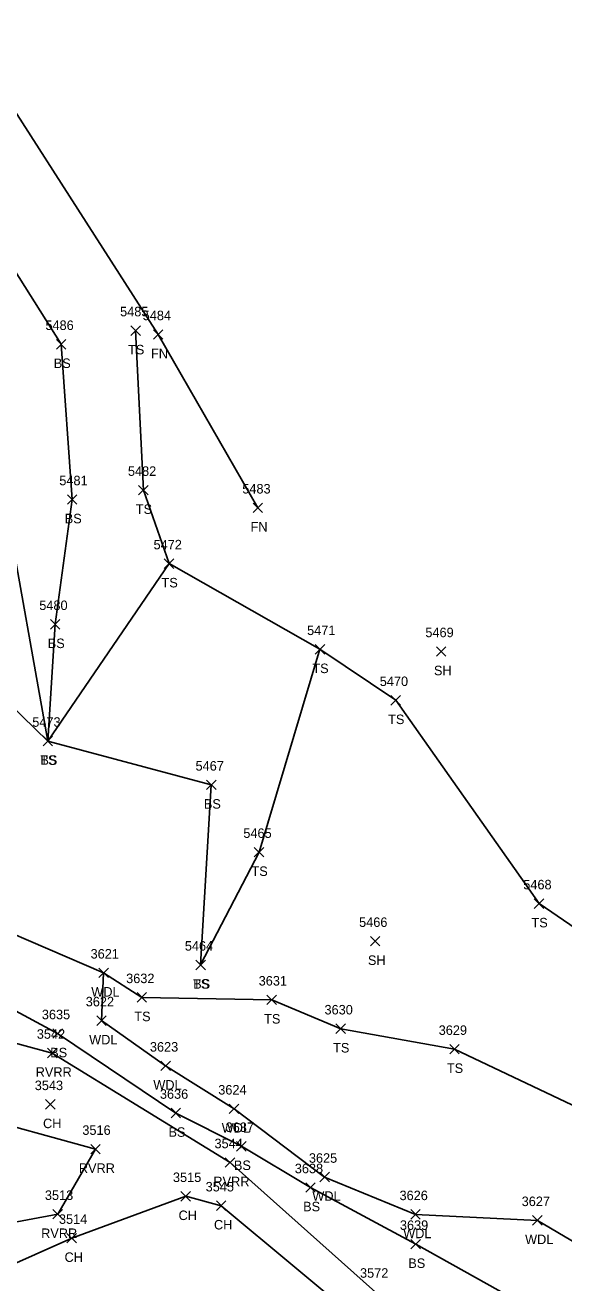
# Model space of a CAD drawing. Extents: x 1601151 to 1602912, y 499508 to 501770.
# Drawn here: x 1601662.3 to 1601775.4, y 500689.8 to 500954.3 of the extents above; entities that cross this region are included whole.
import ezdxf

# ---------------------------------------------------------------- set-up
doc = ezdxf.new("R2010")
doc.units = 0
for name, color, linetype in [('L_A', 7, 'Continuous'), ('L_I', 7, 'Continuous'), ('L_TIC', 7, 'Continuous'), ('LAWA', 7, 'Continuous'), ('LAWE', 7, 'Continuous'), ('LDEFAULT', 7, 'Continuous'), ('LELB', 7, 'Continuous'), ('LFNC', 7, 'Continuous')]:
    doc.layers.add(name, color=color, linetype=linetype)

msp = doc.modelspace()

# ---------------------------------------------------------------- linework, layer by layer
at = {"layer": 'L_TIC'}
for points in [[(1601684.45, 500889.07), (1601686.45, 500891.07)], [(1601686.45, 500889.07), (1601684.45, 500891.07)], [(1601689.2, 500888.26), (1601691.2, 500890.26)], [(1601691.2, 500888.26), (1601689.2, 500890.26)], [(1601668.81, 500886.2), (1601670.81, 500888.2)], [(1601670.81, 500886.2), (1601668.81, 500888.2)], [(1601686.09, 500855.52), (1601688.09, 500857.52)], [(1601688.09, 500855.52), (1601686.09, 500857.52)], [(1601671.12, 500853.54), (1601673.12, 500855.54)], [(1601673.12, 500853.54), (1601671.12, 500855.54)], [(1601710.12, 500851.81), (1601712.12, 500853.81)], [(1601712.12, 500851.81), (1601710.12, 500853.81)], [(1601691.48, 500840.06), (1601693.48, 500842.06)], [(1601693.48, 500840.06), (1601691.48, 500842.06)], [(1601691.48, 500840.06), (1601693.48, 500842.06)], [(1601693.48, 500840.06), (1601691.48, 500842.06)], [(1601667.55, 500827.3), (1601669.55, 500829.3)], [(1601669.55, 500827.3), (1601667.55, 500829.3)], [(1601723.17, 500822.04), (1601725.17, 500824.04)], [(1601725.17, 500822.04), (1601723.17, 500824.04)], [(1601723.17, 500822.04), (1601725.17, 500824.04)], [(1601725.17, 500822.04), (1601723.17, 500824.04)], [(1601748.64, 500821.59), (1601750.64, 500823.59)], [(1601750.64, 500821.59), (1601748.64, 500823.59)], [(1601739.09, 500811.32), (1601741.09, 500813.32)], [(1601741.09, 500811.32), (1601739.09, 500813.32)], [(1601666, 500802.75), (1601668, 500804.75)], [(1601668, 500802.75), (1601666, 500804.75)], [(1601666, 500802.75), (1601668, 500804.75)], [(1601668, 500802.75), (1601666, 500804.75)], [(1601700.34, 500793.53), (1601702.34, 500795.53)], [(1601702.34, 500793.53), (1601700.34, 500795.53)], [(1601710.38, 500779.38), (1601712.38, 500781.38)], [(1601712.38, 500779.38), (1601710.38, 500781.38)], [(1601769.2, 500768.56), (1601771.2, 500770.56)], [(1601771.2, 500768.56), (1601769.2, 500770.56)], [(1601734.77, 500760.66), (1601736.77, 500762.66)], [(1601736.77, 500760.66), (1601734.77, 500762.66)], [(1601698.1, 500755.67), (1601700.1, 500757.67)], [(1601700.1, 500755.67), (1601698.1, 500757.67)], [(1601698.1, 500755.67), (1601700.1, 500757.67)], [(1601700.1, 500755.67), (1601698.1, 500757.67)], [(1601677.73, 500754.01), (1601679.73, 500756.01)], [(1601679.73, 500754.01), (1601677.73, 500756.01)], [(1601685.77, 500748.84), (1601687.77, 500750.84)], [(1601687.77, 500748.84), (1601685.77, 500750.84)], [(1601713.04, 500748.33), (1601715.04, 500750.33)], [(1601715.04, 500748.33), (1601713.04, 500750.33)], [(1601677.28, 500743.95), (1601679.28, 500745.95)], [(1601679.28, 500743.95), (1601677.28, 500745.95)], [(1601727.53, 500742.25), (1601729.53, 500744.25)], [(1601729.53, 500742.25), (1601727.53, 500744.25)], [(1601668.06, 500741.24), (1601670.06, 500743.24)], [(1601670.06, 500741.24), (1601668.06, 500743.24)], [(1601666.95, 500737.14), (1601668.95, 500739.14)], [(1601668.95, 500737.14), (1601666.95, 500739.14)], [(1601751.43, 500737.95), (1601753.43, 500739.95)], [(1601753.43, 500737.95), (1601751.43, 500739.95)], [(1601690.76, 500734.44), (1601692.76, 500736.44)], [(1601692.76, 500734.44), (1601690.76, 500736.44)], [(1601666.52, 500726.34), (1601668.52, 500728.34)], [(1601668.52, 500726.34), (1601666.52, 500728.34)], [(1601692.91, 500724.52), (1601694.91, 500726.52)], [(1601694.91, 500724.52), (1601692.91, 500726.52)], [(1601705.12, 500725.41), (1601707.12, 500727.41)], [(1601707.12, 500725.41), (1601705.12, 500727.41)], [(1601676.01, 500716.93), (1601678.01, 500718.93)], [(1601678.01, 500716.93), (1601676.01, 500718.93)], [(1601706.66, 500717.53), (1601708.66, 500719.53)], [(1601708.66, 500717.53), (1601706.66, 500719.53)], [(1601704.28, 500714.12), (1601706.28, 500716.12)], [(1601706.28, 500714.12), (1601704.28, 500716.12)], [(1601724.16, 500711.06), (1601726.16, 500713.06)], [(1601726.16, 500711.06), (1601724.16, 500713.06)], [(1601721.2, 500708.86), (1601723.2, 500710.86)], [(1601723.2, 500708.86), (1601721.2, 500710.86)], [(1601694.98, 500707.01), (1601696.98, 500709.01)], [(1601696.98, 500707.01), (1601694.98, 500709.01)], [(1601702.42, 500705.03), (1601704.42, 500707.03)], [(1601704.42, 500705.03), (1601702.42, 500707.03)], [(1601668.09, 500703.24), (1601670.09, 500705.24)], [(1601670.09, 500703.24), (1601668.09, 500705.24)], [(1601743.25, 500703.2), (1601745.25, 500705.2)], [(1601745.25, 500703.2), (1601743.25, 500705.2)], [(1601768.86, 500701.95), (1601770.86, 500703.95)], [(1601770.86, 500701.95), (1601768.86, 500703.95)], [(1601671.03, 500698.21), (1601673.03, 500700.21)], [(1601673.03, 500698.21), (1601671.03, 500700.21)], [(1601743.29, 500696.94), (1601745.29, 500698.94)], [(1601745.29, 500696.94), (1601743.29, 500698.94)]]:
    msp.add_lwpolyline(points, dxfattribs=at)
at = {"layer": 'LAWA'}
msp.add_lwpolyline([(1601593.12, 500801.88), (1601615.83, 500798.98), (1601635.32, 500780.93), (1601655.21, 500765.08), (1601678.73, 500755.01), (1601678.28, 500744.95), (1601691.76, 500735.44), (1601706.12, 500726.41), (1601725.16, 500712.06), (1601744.25, 500704.2), (1601769.86, 500702.95), (1601803.71, 500682.95)], dxfattribs=at)
at = {"layer": 'LAWE'}
for points in [[(1601318.62, 500789.62), (1601362.93, 500806.22), (1601394.46, 500804.48), (1601434.19, 500795.17), (1601527.96, 500788.91), (1601546.38, 500778.25), (1601558, 500777.29), (1601574.08, 500771.8), (1601598.01, 500757.12), (1601667.95, 500738.14), (1601705.28, 500715.12), (1601735.85, 500687.88), (1601768.33, 500671.26), (1601783.77, 500659.22)], [(1601521.09, 500757.43), (1601560.31, 500712.79), (1601565, 500710.16), (1601565.18, 500704.96), (1601578.99, 500700.46), (1601594.09, 500700.38), (1601635.3, 500697.93), (1601669.09, 500704.24), (1601677.01, 500717.93), (1601649.99, 500725.34), (1601626.36, 500742.54), (1601583.16, 500733.4), (1601587.17, 500723.02)]]:
    msp.add_lwpolyline(points, dxfattribs=at)
at = {"layer": 'LDEFAULT'}
msp.add_lwpolyline([(1601337.45, 500787.94), (1601362.97, 500800.69), (1601393.84, 500792.74), (1601431.56, 500786.24), (1601466, 500759.52), (1601526, 500726.82), (1601566.27, 500697.9), (1601580.09, 500695.39), (1601593.87, 500695.15), (1601641.19, 500685.49), (1601672.03, 500699.21), (1601695.98, 500708.01), (1601703.42, 500706.03), (1601734.4, 500680.19), (1601767.36, 500664.87), (1601779.68, 500657.31)], dxfattribs=at)
at = {"layer": 'LELB'}
for points in [[(1601668.55, 500828.3), (1601672.12, 500854.54), (1601669.81, 500887.2), (1601657.78, 500906.35), (1601643.71, 500902.26), (1601640.63, 500885.16), (1601616.51, 500885.81), (1601612.17, 500898.48), (1601610.89, 500931.33), (1601622.98, 500925.22), (1601641.29, 500922.99)], [(1601770.2, 500769.56), (1601740.09, 500812.32), (1601724.17, 500823.04), (1601692.48, 500841.06), (1601687.09, 500856.52), (1601685.45, 500890.07)], [(1601692.48, 500841.06), (1601667, 500803.75), (1601658.09, 500853.77)], [(1601699.1, 500756.67), (1601701.34, 500794.53), (1601667, 500803.75), (1601645.29, 500824.82), (1601639.58, 500836.48), (1601632.39, 500841.14), (1601619.85, 500820.05)], [(1601667, 500803.75), (1601668.55, 500828.3)], [(1601699.1, 500756.67), (1601711.38, 500780.38), (1601724.17, 500823.04)], [(1601558.48, 500782.72), (1601575.06, 500777.59), (1601597.78, 500761.54), (1601614.66, 500759.88), (1601621.4, 500771.94), (1601644.48, 500755.47), (1601669.06, 500742.24), (1601693.91, 500725.52), (1601707.66, 500718.53), (1601722.2, 500709.86), (1601744.29, 500697.94), (1601771.8, 500682.56), (1601891.41, 500620.78)], [(1601770.2, 500769.56), (1601833.3, 500726.33)], [(1601678.73, 500755.01), (1601686.77, 500749.84)], [(1601779.9, 500725.89), (1601752.43, 500738.95), (1601728.53, 500743.25), (1601714.04, 500749.33), (1601686.77, 500749.84)]]:
    msp.add_lwpolyline(points, dxfattribs=at)
at = {"layer": 'LFNC'}
msp.add_lwpolyline([(1601711.12, 500852.81), (1601690.2, 500889.26), (1601642.99, 500962.95)], dxfattribs=at)

# ---------------------------------------------------------------- texts
at = {"layer": 'L_A'}
for s, p in [('TS', (1601683.86, 500885.07)), ('BS', (1601668.25, 500882.2)), ('FN', (1601688.68, 500884.26)), ('TS', (1601685.5, 500851.52)), ('BS', (1601670.56, 500849.54)), ('FN', (1601709.6, 500847.81)), ('TS', (1601690.89, 500836.06)), ('TS', (1601690.89, 500836.06)), ('BS', (1601666.99, 500823.3)), ('TS', (1601722.58, 500818.04)), ('TS', (1601722.58, 500818.04)), ('SH', (1601748.12, 500817.59)), ('TS', (1601738.5, 500807.32)), ('TS', (1601665.41, 500798.75)), ('BS', (1601665.44, 500798.75)), ('BS', (1601699.79, 500789.53)), ('TS', (1601709.79, 500775.38)), ('TS', (1601768.61, 500764.56)), ('SH', (1601734.25, 500756.66)), ('WDL', (1601676.14, 500750.01)), ('TS', (1601697.51, 500751.67)), ('BS', (1601697.54, 500751.67)), ('TS', (1601685.18, 500744.84)), ('TS', (1601712.45, 500744.33)), ('WDL', (1601675.69, 500739.95)), ('BS', (1601667.5, 500737.24)), ('TS', (1601726.94, 500738.25)), ('TS', (1601750.84, 500733.95)), ('RVRR', (1601664.46, 500733.14)), ('WDL', (1601689.17, 500730.44)), ('CH', (1601666, 500722.34)), ('BS', (1601692.35, 500720.52)), ('WDL', (1601703.54, 500721.41)), ('RVRR', (1601673.52, 500712.93)), ('BS', (1601706.1, 500713.53)), ('RVRR', (1601701.79, 500710.12)), ('WDL', (1601722.57, 500707.06)), ('BS', (1601720.64, 500704.86)), ('CH', (1601694.47, 500703.01)), ('RVRR', (1601665.6, 500699.24)), ('CH', (1601701.91, 500701.03)), ('WDL', (1601741.67, 500699.2)), ('WDL', (1601767.27, 500697.95)), ('CH', (1601670.52, 500694.21)), ('BS', (1601742.73, 500692.94))]:
    msp.add_text(s, height=2, dxfattribs=at).set_placement(p)
at = {"layer": 'L_I'}
for s, p in [('5485', (1601682.19, 500893.07)), ('5484', (1601686.94, 500892.26)), ('5486', (1601666.5, 500890.2)), ('5482', (1601683.83, 500859.52)), ('5481', (1601669.42, 500857.54)), ('5483', (1601707.86, 500855.81)), ('5472', (1601689.22, 500844.06)), ('5472', (1601689.22, 500844.06)), ('5480', (1601665.21, 500831.3)), ('5471', (1601721.48, 500826.04)), ('5471', (1601721.48, 500826.04)), ('5469', (1601746.32, 500825.59)), ('5470', (1601736.74, 500815.32)), ('5473', (1601663.74, 500806.75)), ('5473', (1601663.74, 500806.75)), ('5467', (1601698.04, 500797.53)), ('5465', (1601708.08, 500783.38)), ('5468', (1601766.89, 500772.56)), ('5466', (1601732.4, 500764.66)), ('3621', (1601675.99, 500758.01)), ('5464', (1601695.79, 500759.67)), ('5464', (1601695.79, 500759.67)), ('3632', (1601683.46, 500752.84)), ('3631', (1601711.3, 500752.33)), ('3622', (1601674.97, 500747.95)), ('3635', (1601665.75, 500745.24)), ('3630', (1601725.13, 500746.25)), ('3629', (1601749.12, 500741.95)), ('3542', (1601664.69, 500741.14)), ('3623', (1601688.45, 500738.44)), ('3543', (1601664.26, 500730.34)), ('3636', (1601690.55, 500728.52)), ('3624', (1601702.81, 500729.41)), ('3516', (1601674.26, 500720.93)), ('3637', (1601704.36, 500721.53)), ('3544', (1601702.02, 500718.12)), ('3625', (1601721.85, 500715.06)), ('3638', (1601718.89, 500712.86)), ('3515', (1601693.29, 500711.01)), ('3513', (1601666.39, 500707.24)), ('3545', (1601700.16, 500709.03)), ('3626', (1601740.89, 500707.2)), ('3627', (1601766.55, 500705.95)), ('3514', (1601669.34, 500702.21)), ('3639', (1601740.97, 500700.94)), ('3572', (1601732.59, 500690.88))]:
    msp.add_text(s, height=2, dxfattribs=at).set_placement(p)

doc.saveas('drawing.dxf')
